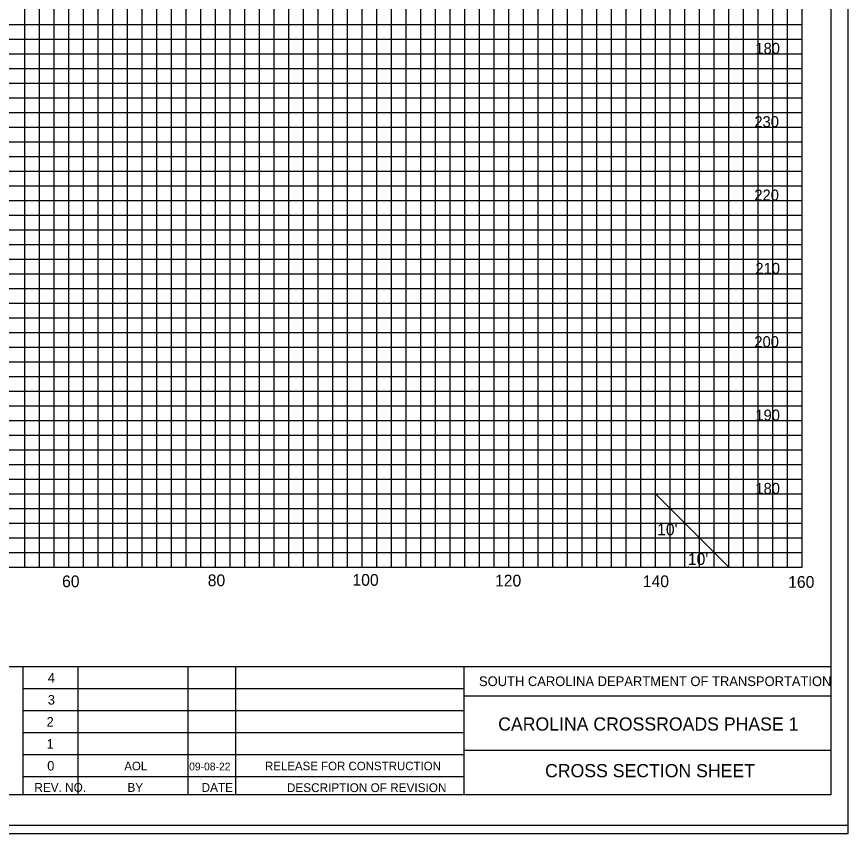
# Model space of a CAD drawing. Extents: x 967 to 1326, y 964 to 2584.
# Drawn here: x 1212.9 to 1326.3, y 1523.7 to 1635.1 of the extents above; entities that cross this region are included whole.
import ezdxf

# ---------------------------------------------------------------- set-up
doc = ezdxf.new("R2010")
doc.units = 0
for name, color, linetype in [('Default', 7, 'Continuous'), ('RD_SHT_Bndy', 7, 'Continuous'), ('RD_SHT_IplotShp', 7, 'Continuous'), ('RD_SHT_Misc1', 7, 'Continuous'), ('RD_SHT_MjGrid', 7, 'Continuous'), ('RD_SHT_MnGrid', 7, 'Continuous'), ('RD_SHT_TX', 7, 'Continuous'), ('RD_Sketch1', 7, 'Continuous')]:
    doc.layers.add(name, color=color, linetype=linetype)

msp = doc.modelspace()

# ---------------------------------------------------------------- linework, layer by layer
at = {"layer": 'RD_SHT_Bndy'}
for p, q in [((1323.89, 1738.46), (1323.89, 1528.98)), ((996.11, 1546.49), (1323.89, 1546.49)), ((1213.76, 1528.94), (1213.76, 1546.49)), ((1221.26, 1528.95), (1221.26, 1546.48)), ((1236.26, 1528.95), (1236.26, 1546.48)), ((1242.76, 1528.95), (1242.76, 1546.48)), ((1273.88, 1528.98), (1273.88, 1546.49)), ((1213.76, 1543.48), (1273.88, 1543.48)), ((1323.93, 1542.43), (1273.88, 1542.43)), ((1213.76, 1540.48), (1273.88, 1540.48)), ((1213.76, 1537.48), (1273.88, 1537.48)), ((1213.76, 1534.48), (1273.88, 1534.48)), ((1323.89, 1535.04), (1273.88, 1535.04)), ((1213.76, 1531.48), (1273.88, 1531.48)), ((1323.89, 1528.98), (996.11, 1528.98))]:
    msp.add_line(p, q, dxfattribs=at)
at = {"layer": 'RD_SHT_IplotShp'}
for points in [[(967.41, 1523.72), (1326.28, 1523.72), (1326.28, 1743.72), (967.41, 1743.72)], [(988.52, 1524.84), (1326.28, 1524.84), (1326.28, 1742.6), (988.52, 1742.6)]]:
    msp.add_lwpolyline(points, close=True, dxfattribs=at)
at = {"layer": 'RD_SHT_MjGrid'}
for p, q in [((1220, 1560), (1220, 1730)), ((1230, 1560), (1230, 1730)), ((1240, 1560), (1240, 1730)), ((1250, 1560), (1250, 1730)), ((1260, 1560), (1260, 1730)), ((1270, 1560), (1270, 1730)), ((1280, 1560), (1280, 1730)), ((1290, 1560), (1290, 1730)), ((1300, 1560), (1300, 1730)), ((1310, 1560), (1310, 1730)), ((1320, 1560), (1320, 1730)), ((1000, 1630), (1320, 1630)), ((1000, 1620), (1320, 1620)), ((1000, 1610), (1320, 1610)), ((1000, 1600), (1320, 1600)), ((1000, 1590), (1320, 1590)), ((1000, 1580), (1320, 1580)), ((1000, 1570), (1320, 1570)), ((1000, 1560), (1320, 1560))]:
    msp.add_line(p, q, dxfattribs=at)
at = {"layer": 'RD_SHT_MnGrid'}
for p, q in [((1214, 1560), (1214, 1730)), ((1216, 1560), (1216, 1730)), ((1218, 1560), (1218, 1730)), ((1222, 1560), (1222, 1730)), ((1224, 1560), (1224, 1730)), ((1226, 1560), (1226, 1730)), ((1228, 1560), (1228, 1730)), ((1232, 1560), (1232, 1730)), ((1234, 1560), (1234, 1730)), ((1236, 1560), (1236, 1730)), ((1238, 1560), (1238, 1730)), ((1242, 1560), (1242, 1730)), ((1244, 1560), (1244, 1730)), ((1246, 1560), (1246, 1730)), ((1248, 1560), (1248, 1730)), ((1252, 1560), (1252, 1730)), ((1254, 1560), (1254, 1730)), ((1256, 1560), (1256, 1730)), ((1258, 1560), (1258, 1730)), ((1262, 1560), (1262, 1730)), ((1264, 1560), (1264, 1730)), ((1266, 1560), (1266, 1730)), ((1268, 1560), (1268, 1730)), ((1272, 1560), (1272, 1730)), ((1274, 1560), (1274, 1730)), ((1276, 1560), (1276, 1730)), ((1278, 1560), (1278, 1730)), ((1282, 1560), (1282, 1730)), ((1284, 1560), (1284, 1730)), ((1286, 1560), (1286, 1730)), ((1288, 1560), (1288, 1730)), ((1292, 1560), (1292, 1730)), ((1294, 1560), (1294, 1730)), ((1296, 1560), (1296, 1730)), ((1298, 1560), (1298, 1730)), ((1302, 1560), (1302, 1730)), ((1304, 1560), (1304, 1730)), ((1306, 1560), (1306, 1730)), ((1308, 1560), (1308, 1730)), ((1312, 1560), (1312, 1730)), ((1314, 1560), (1314, 1730)), ((1316, 1560), (1316, 1730)), ((1318, 1560), (1318, 1730)), ((1000, 1634), (1320, 1634)), ((1000, 1632), (1320, 1632)), ((1000, 1628), (1320, 1628)), ((1000, 1626), (1320, 1626)), ((1000, 1624), (1320, 1624)), ((1000, 1622), (1320, 1622)), ((1000, 1618), (1320, 1618)), ((1000, 1616), (1320, 1616)), ((1000, 1614), (1320, 1614)), ((1000, 1612), (1320, 1612)), ((1000, 1608), (1320, 1608)), ((1000, 1606), (1320, 1606)), ((1000, 1604), (1320, 1604)), ((1000, 1602), (1320, 1602)), ((1000, 1598), (1320, 1598)), ((1000, 1596), (1320, 1596)), ((1000, 1594), (1320, 1594)), ((1000, 1592), (1320, 1592)), ((1000, 1588), (1320, 1588)), ((1000, 1586), (1320, 1586)), ((1000, 1584), (1320, 1584)), ((1000, 1582), (1320, 1582)), ((1000, 1578), (1320, 1578)), ((1000, 1576), (1320, 1576)), ((1000, 1574), (1320, 1574)), ((1000, 1572), (1320, 1572)), ((1000, 1568), (1320, 1568)), ((1000, 1566), (1320, 1566)), ((1000, 1564), (1320, 1564)), ((1000, 1562), (1320, 1562))]:
    msp.add_line(p, q, dxfattribs=at)
at = {"layer": 'RD_SHT_TX'}
msp.add_line((1300, 1570), (1310, 1560), dxfattribs=at)
at = {"layer": 'RD_Sketch1'}
msp.add_lwpolyline([(967.41, 1523.72), (1326.28, 1523.72), (1326.28, 1743.72), (967.41, 1743.72)], close=True, dxfattribs=at)

# ---------------------------------------------------------------- texts
at = {"layer": 'Default'}
for s, p in [('180', (1313.61, 1630)), ('230', (1313.47, 1620)), ('220', (1313.47, 1610)), ('210', (1313.61, 1600)), ('200', (1313.47, 1590)), ('190', (1313.61, 1580)), ('180', (1313.61, 1570))]:
    msp.add_text(s, height=1.5, dxfattribs=at).set_placement(p)
at = {"layer": 'RD_SHT_Misc1'}
for s, height, p in [('AOL', 1.17, (1227.56, 1532.32)), ('09-08-22', 1.053, (1236.4, 1532.31)), ('RELEASE FOR CONSTRUCTION', 1.17, (1246.74, 1532.32))]:
    msp.add_text(s, height=height, dxfattribs=at).set_placement(p)
at = {"layer": 'RD_SHT_TX'}
for s, height, p in [("10'", 1.6, (1300.21, 1564.36)), ("10'", 1.6, (1304.4, 1560.32)), ('60', 1.6, (1219.08, 1557.28)), ('80', 1.6, (1238.94, 1557.42)), ('100', 1.6, (1258.67, 1557.48)), ('120', 1.6, (1278.11, 1557.38)), ('140', 1.6, (1298.26, 1557.29)), ('160', 1.6, (1318.08, 1557.2)), ('4', 1.3, (1217.13, 1544.28)), ('SOUTH CAROLINA DEPARTMENT OF TRANSPORTATION', 1.32, (1275.92, 1543.8)), ('3', 1.3, (1217.13, 1541.28)), ('2', 1.3, (1216.97, 1538.28)), ('1', 1.3, (1216.97, 1535.28)), ('0', 1.3, (1217.05, 1532.28)), ('REV. NO.', 1.2, (1215.3, 1529.38)), ('BY', 1.2, (1227.99, 1529.38)), ('DATE', 1.2, (1238.1, 1529.38)), ('DESCRIPTION OF REVISION', 1.2, (1249.73, 1529.35))]:
    msp.add_text(s, height=height, dxfattribs=at).set_placement(p)
for s, p in [('CAROLINA CROSSROADS PHASE 1', (1278.54, 1537.73)), ('CROSS SECTION SHEET', (1284.93, 1531.37))]:
    msp.add_text(s, height=1.8, rotation=0, dxfattribs=at).set_placement(p)

doc.saveas('drawing.dxf')
